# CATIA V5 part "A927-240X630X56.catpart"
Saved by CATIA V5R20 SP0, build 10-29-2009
Part number: A927-240X630X56
Source: Unknown
Property "A": "160.000"
Property "ARTICLENO": "A927-240X630X56"
Property "BOMINFO": "A927-240X630X56"
Property "CODE": "A927-240X630X56"
Property "CREATOR": "CADENAS GmbH"
Property "D": "26.000"
Property "D1": "40.000"
Property "F": "36.000"
Property "FORM": "B"
Property "L": "630.000"
Property "L1": "250.000"
Property "L2": "40.000"
Property "L3": "160.000"
Property "LINA": "A927-240X630X56"
Property "NB": "A927-240X630X56"
Property "NBSYN": "$CODE."
Property "NN": "A927"
Property "NT": "VDI 3387 Removable Die Heels, steel and self-lubricating"
Property "R": "31.500"
Property "S": "56.000"
Property "SUPPLIER": "CF"
Property "T": "30.500"
Property "W": "240.000"
Bounding box of the stored display mesh (mm): x -120 to 120, y 0 to 630, z -56 to 0
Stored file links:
  C:\Users\borellobunino\Desktop\3D X SITO CF\A927\GSB_OILLESS_G2290524063056\CATIAV5\A927-240X630X56.catpart
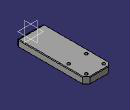
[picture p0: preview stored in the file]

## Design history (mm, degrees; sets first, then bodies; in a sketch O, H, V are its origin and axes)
Body1 "Geometry.1" (main body)
  Solid1 "A927-240X630X56.catpart": solid without history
